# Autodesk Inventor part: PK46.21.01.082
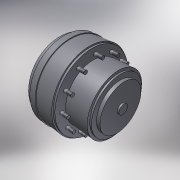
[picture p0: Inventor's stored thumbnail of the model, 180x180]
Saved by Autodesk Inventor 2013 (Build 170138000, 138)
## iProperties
Created: 2005-03
Part Number: PK46.21.01.082
Material: Steel, Mild
Document SubType Name: Modeling
Designer: salex
Manufacturer: Standard
Standards Organization: Custom
Density: 7.86 g/cm^3
Mass: 456764 g
Surface Area: 9789.41 cm^2
Volume: 58112.5 cm^3
Author: salex
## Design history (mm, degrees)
revolve "Вращение1" stored, may be unused: angle "d20" = 90 deg
sketch "Эскиз2"
  geometry: C1 r 185 at (0, 0) reference; C2 r 11 at (-207.5, 0)
  constraints: 1 centre point
  dimensions: "d21" = 22 diameter of C2; "d22" = 0 vertical distance of C1.centre C2.centre; "d23" = 207.5 distance of C1.centre C2.centre
extrude "Выдавливание1" join sketch "Эскиз2" distance "d24" = 45; taper "d25" = 0 deg
thread "Thread1" dims "d29" = 30, "d30" = 0
pattern_circular "Круговой массив1" dims angle "d28" = 360 deg
body "Solid1"
sketch "Эскиз1"
  geometry: L1 (0, 0)-(417, 0); L2 (0, 0)-(0, 120.442); L3 (0, 120.442)-(45, 132.5); L4 (45, 132.5)-(45, 240); L5 (45, 240)-(80, 240); L6 (80, 240)-(80, 257.5); L7 (80, 257.5)-(120, 257.5); L8 (120, 257.5)-(120, 252.5); L9 (120, 252.5)-(230, 252.5); L10 (230, 252.5)-(230, 245); L11 (230, 245)-(242, 245); L12 (242, 245)-(242, 185); L13 (242, 185)-(377, 185); L14 (377, 185)-(377, 170); L15 (377, 170)-(387, 170); L16 (387, 170)-(387, 140); L17 (387, 140)-(407, 140); L18 (407, 140)-(407, 30); L19 (407, 30)-(417, 30); L20 (417, 30)-(417, 0)
  constraints: 40 end point, 14 parallel, 4 perpendicular, 1 horizontal, 1 other
  dimensions: "d0" = 60 diameter of L19 L1; "d1" = 10 distance of L18.end L19.end; "d2" = 280 diameter of L17 L1; "d3" = 20 distance of L16.end L17.end; "d4" = 340 diameter of L15 L1; "d5" = 10 distance of L14.end L15.end; "d6" = 135 distance of L12.end L13.end; "d7" = 370 diameter of L13 L1; "d9" = 490 diameter of L11 L1; "d10" = 12 distance of L10.end L11.end; "d11" = 515 diameter of L7 L1; "d12" = 505 diameter of L9 L1; "d13" = 242 distance between parallel lines of L12 L2; "d14" = 40 distance of L6.end L7.end; "d15" = 80 distance between parallel lines of L6 L2; "d16" = 35 distance of L4.end L5.end; "d17" = 105 deg angle of L2 L3; "d18" = 480 diameter of L5 L1; "d19" = 265 diameter of L3.end L1
